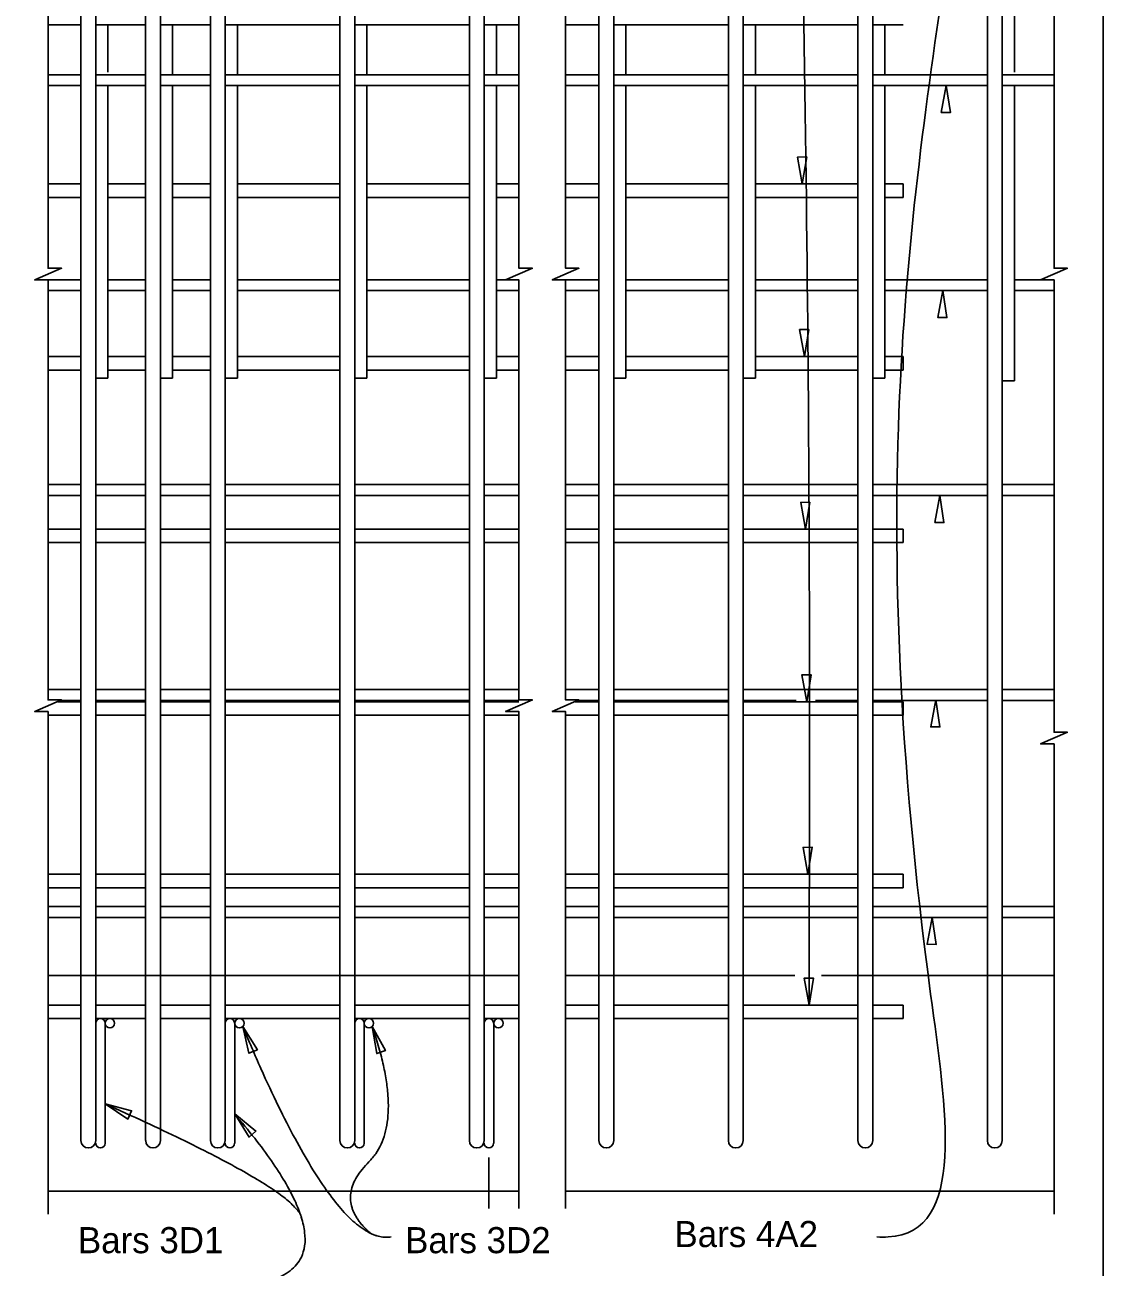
# Model space of a CAD drawing. Extents: x 0 to 20.5, y 0 to 12.9.
# Drawn here: x 16.322 to 20.485, y 4.445 to 9.244 of the extents above; entities that cross this region are included whole.
import ezdxf

# ---------------------------------------------------------------- set-up
doc = ezdxf.new("R2010")
doc.units = 0
for name, color, linetype in [('ActivePts-ConstElements', 7, 'Continuous'), ('BeamConc', 7, 'Continuous'), ('BeamConc_h', 7, 'Continuous'), ('Dimension', 7, 'Continuous'), ('Rebar', 7, 'Continuous'), ('TextStructures', 7, 'Continuous')]:
    doc.layers.add(name, color=color, linetype=linetype)

msp = doc.modelspace()

# ---------------------------------------------------------------- linework, layer by layer
at = {"layer": 'ActivePts-ConstElements'}
msp.add_lwpolyline([(0, 12.9475), (20.485, 12.9475), (20.485, 0), (0, 0)], close=True, dxfattribs=at)
at = {"layer": 'BeamConc'}
for p, q in [((16.4116, 4.739), (18.2295, 4.739)), ((18.4095, 4.739), (20.2953, 4.739))]:
    msp.add_line(p, q, dxfattribs=at)
at = {"layer": 'BeamConc_h'}
for p, q in [((16.4116, 5.5723), (18.2295, 5.5723)), ((18.4095, 5.5723), (19.2946, 5.5723)), ((19.3975, 5.5723), (20.2953, 5.5723))]:
    msp.add_line(p, q, dxfattribs=at)
at = {"layer": 'Dimension'}
msp.add_line((18.1135, 4.8686), (18.1135, 4.6717), dxfattribs=at)
for points in [[(16.4116, 10.0723), (16.4116, 8.3039), (16.4633, 8.3039), (16.36, 8.2589), (16.4116, 8.2589), (16.4116, 6.6365), (16.4633, 6.6365), (16.36, 6.5915), (16.4116, 6.5915), (16.4116, 4.6506)], [(18.2295, 10.0723), (18.2295, 8.3039), (18.2812, 8.3039), (18.1778, 8.2589), (18.2295, 8.2589), (18.2295, 6.6365), (18.2812, 6.6365), (18.1778, 6.5915), (18.2295, 6.5915), (18.2295, 4.6717)], [(18.4095, 10.0723), (18.4095, 8.3039), (18.4612, 8.3039), (18.3579, 8.2589), (18.4095, 8.2589), (18.4095, 6.6365), (18.4612, 6.6365), (18.3579, 6.5915), (18.4095, 6.5915), (18.4095, 4.6717)], [(20.2953, 10.0723), (20.2953, 8.3039), (20.347, 8.3039), (20.2437, 8.2589), (20.2953, 8.2589), (20.2953, 6.5115), (20.347, 6.5115), (20.2437, 6.4665), (20.2953, 6.4665), (20.2953, 4.6506)]]:
    msp.add_lwpolyline(points, dxfattribs=at)
for points in [[(19.8792, 9.0099), (19.8601, 8.906), (19.8953, 8.9055)], [(19.3235, 8.6296), (19.3404, 8.7339), (19.3051, 8.7336)], [(19.8656, 8.2178), (19.8465, 8.1139), (19.8818, 8.1134)], [(19.3313, 7.9628), (19.3482, 8.067), (19.3129, 8.0668)], [(19.3355, 7.2956), (19.3525, 7.3999), (19.3172, 7.3996)], [(19.8543, 7.4259), (19.8352, 7.3221), (19.8704, 7.3216)], [(19.3403, 6.6295), (19.3572, 6.7338), (19.322, 6.7335)], [(19.8387, 6.6364), (19.8196, 6.5325), (19.8549, 6.532)], [(19.3451, 5.9629), (19.362, 6.0671), (19.3267, 6.0669)], [(19.8246, 5.7963), (19.8055, 5.6925), (19.8408, 5.692)], [(19.3494, 5.4578), (19.3664, 5.562), (19.3311, 5.5618)], [(17.1629, 5.3745), (17.1867, 5.2716), (17.2193, 5.2852)], [(17.6629, 5.3745), (17.6802, 5.2703), (17.7135, 5.2818)], [(16.6318, 5.0758), (16.7197, 5.0172), (16.734, 5.0494)], [(17.1318, 5.0372), (17.1876, 4.9476), (17.214, 4.9709)]]:
    msp.add_lwpolyline(points, close=True, dxfattribs=at)
for points in [[(19.5169, 10.7039), (19.4625, 10.7051), (19.3121, 10.2105), (19.3494, 5.4578)], [(19.6115, 4.5619), (19.6547, 4.5619), (19.819, 5.4995), (19.8873, 9.5318)]]:
    msp.add_spline(points, degree=3, dxfattribs=at)
for points in [[(17.7362, 4.5622), (17.5173, 4.5252), (17.1629, 5.3745)], [(17.6567, 4.5757), (17.5049, 4.7071), (17.7938, 4.995), (17.6629, 5.3745)], [(17.3904, 4.6335), (17.3739, 4.7442), (16.6318, 5.0758)], [(17.0406, 4.3694), (17.7177, 4.3524), (17.1318, 5.0372)]]:
    msp.add_open_spline(points, degree=2, dxfattribs=at)
at = {"layer": 'Rebar'}
for p, q in [((16.5953, 4.9343), (16.5953, 10.4187)), ((16.8453, 4.9343), (16.8453, 10.4187)), ((17.0953, 4.9343), (17.0953, 10.4187)), ((17.5953, 4.9343), (17.5953, 10.4187)), ((18.0953, 4.9343), (18.0953, 10.4187)), ((18.5953, 4.9343), (18.5953, 10.4187)), ((19.0953, 4.9343), (19.0953, 10.4187)), ((19.5953, 4.9343), (19.5953, 10.4187)), ((20.0953, 4.9343), (20.0953, 10.4187)), ((20.1422, 9.0619), (20.1422, 9.8475)), ((16.538, 4.9343), (16.538, 9.5318)), ((16.788, 4.9343), (16.788, 9.5318)), ((17.038, 4.9343), (17.038, 9.5318)), ((17.538, 4.9343), (17.538, 9.5318)), ((18.038, 4.9343), (18.038, 9.5318)), ((18.538, 4.9343), (18.538, 9.5318)), ((19.038, 4.9343), (19.038, 9.5318)), ((19.538, 4.9343), (19.538, 9.5318)), ((20.038, 4.9343), (20.038, 9.5318)), ((16.4116, 9.2443), (16.538, 9.2443)), ((16.5953, 9.2443), (16.788, 9.2443)), ((16.6422, 9.0619), (16.6422, 9.2443)), ((16.8453, 9.2443), (17.038, 9.2443)), ((16.8922, 9.0515), (16.8922, 9.2443)), ((17.0953, 9.2443), (17.538, 9.2443)), ((17.1422, 9.0515), (17.1422, 9.2443)), ((17.5953, 9.2443), (18.038, 9.2443)), ((17.6422, 9.0515), (17.6422, 9.2443)), ((18.0953, 9.2443), (18.2295, 9.2443)), ((18.1422, 9.0515), (18.1422, 9.2443)), ((18.4095, 9.2443), (18.538, 9.2443)), ((18.5953, 9.2443), (19.038, 9.2443)), ((18.6422, 9.0515), (18.6422, 9.2443)), ((19.0953, 9.2443), (19.538, 9.2443)), ((19.1422, 9.0515), (19.1422, 9.2443)), ((19.5953, 9.2443), (19.7125, 9.2443)), ((19.6422, 9.0515), (19.6422, 9.2443)), ((16.4116, 9.0515), (16.538, 9.0515)), ((16.5953, 9.0515), (16.788, 9.0515)), ((16.8453, 9.0515), (17.038, 9.0515)), ((17.0953, 9.0515), (17.538, 9.0515)), ((17.5953, 9.0515), (18.038, 9.0515)), ((18.0953, 9.0515), (18.2295, 9.0515)), ((18.4095, 9.0515), (18.538, 9.0515)), ((18.5953, 9.0515), (19.038, 9.0515)), ((19.0953, 9.0515), (19.538, 9.0515)), ((19.5953, 9.0515), (20.038, 9.0515)), ((20.0953, 9.0515), (20.2953, 9.0515)), ((16.4116, 9.0099), (16.538, 9.0099)), ((16.5953, 9.0099), (16.788, 9.0099)), ((16.6422, 7.8796), (16.6422, 9.0099)), ((16.8453, 9.0099), (17.038, 9.0099)), ((16.8922, 7.8796), (16.8922, 9.0099)), ((17.0953, 9.0099), (17.538, 9.0099)), ((17.1422, 7.8796), (17.1422, 9.0099)), ((17.5953, 9.0099), (18.038, 9.0099)), ((17.6422, 7.8796), (17.6422, 9.0099)), ((18.0953, 9.0099), (18.2295, 9.0099)), ((18.1422, 7.8796), (18.1422, 9.0099)), ((18.4095, 9.0099), (18.538, 9.0099)), ((18.5953, 9.0099), (19.038, 9.0099)), ((18.6422, 7.8796), (18.6422, 9.0099)), ((19.0953, 9.0099), (19.538, 9.0099)), ((19.1422, 7.8796), (19.1422, 9.0099)), ((19.5953, 9.0099), (20.038, 9.0099)), ((19.6422, 7.8796), (19.6422, 9.0099)), ((20.0953, 9.0099), (20.2953, 9.0099)), ((20.1422, 7.8692), (20.1422, 9.0099)), ((16.4116, 8.6296), (16.538, 8.6296)), ((16.6422, 8.6296), (16.788, 8.6296)), ((16.8922, 8.6296), (17.038, 8.6296)), ((17.1422, 8.6296), (17.538, 8.6296)), ((17.6422, 8.6296), (18.038, 8.6296)), ((18.1422, 8.6296), (18.2295, 8.6296)), ((18.4095, 8.6296), (18.538, 8.6296)), ((18.6422, 8.6296), (19.038, 8.6296)), ((19.1422, 8.6296), (19.538, 8.6296)), ((19.6422, 8.6296), (19.7125, 8.6296)), ((19.7125, 8.6296), (19.7125, 8.5776)), ((16.4116, 8.5776), (16.538, 8.5776)), ((16.6422, 8.5776), (16.788, 8.5776)), ((16.8922, 8.5776), (17.038, 8.5776)), ((17.1422, 8.5776), (17.538, 8.5776)), ((17.6422, 8.5776), (18.038, 8.5776)), ((18.1422, 8.5776), (18.2295, 8.5776)), ((18.4095, 8.5776), (18.538, 8.5776)), ((18.6422, 8.5776), (19.038, 8.5776)), ((19.1422, 8.5776), (19.538, 8.5776)), ((19.6422, 8.5776), (19.7125, 8.5776)), ((16.4116, 8.2598), (16.538, 8.2598)), ((16.6422, 8.2598), (16.788, 8.2598)), ((16.8922, 8.2598), (17.038, 8.2598)), ((17.1422, 8.2598), (17.538, 8.2598)), ((17.6422, 8.2598), (18.038, 8.2598)), ((18.1422, 8.2598), (18.2295, 8.2598)), ((18.4095, 8.2598), (18.538, 8.2598)), ((18.6422, 8.2598), (19.038, 8.2598)), ((19.1422, 8.2598), (19.538, 8.2598)), ((19.6422, 8.2598), (20.038, 8.2598)), ((20.1422, 8.2598), (20.2953, 8.2598)), ((16.4116, 8.2182), (16.538, 8.2182)), ((16.6422, 8.2182), (16.788, 8.2182)), ((16.8922, 8.2182), (17.038, 8.2182)), ((17.1422, 8.2182), (17.538, 8.2182)), ((17.6422, 8.2182), (18.038, 8.2182)), ((18.1422, 8.2182), (18.2295, 8.2182)), ((18.4095, 8.2182), (18.538, 8.2182)), ((18.6422, 8.2182), (19.038, 8.2182)), ((19.1422, 8.2182), (19.538, 8.2182)), ((19.6422, 8.2182), (20.038, 8.2182)), ((20.1422, 8.2182), (20.2953, 8.2182)), ((16.4116, 7.9629), (16.538, 7.9629)), ((16.6422, 7.9629), (16.788, 7.9629)), ((16.8922, 7.9629), (17.038, 7.9629)), ((17.1422, 7.9629), (17.538, 7.9629)), ((17.6422, 7.9629), (18.038, 7.9629)), ((18.1422, 7.9629), (18.2295, 7.9629)), ((18.4095, 7.9629), (18.538, 7.9629)), ((18.6422, 7.9629), (19.038, 7.9629)), ((19.1422, 7.9629), (19.538, 7.9629)), ((19.6422, 7.9629), (19.7125, 7.9629)), ((19.7125, 7.9629), (19.7125, 7.9109)), ((16.4116, 7.9109), (16.538, 7.9109)), ((16.6422, 7.8796), (16.5953, 7.8796)), ((16.6422, 7.9109), (16.788, 7.9109)), ((16.8922, 7.8796), (16.8453, 7.8796)), ((16.8922, 7.9109), (17.038, 7.9109)), ((17.1422, 7.8796), (17.0953, 7.8796)), ((17.1422, 7.9109), (17.538, 7.9109)), ((17.6422, 7.8796), (17.5953, 7.8796)), ((17.6422, 7.9109), (18.038, 7.9109)), ((18.1422, 7.8796), (18.0953, 7.8796)), ((18.1422, 7.9109), (18.2295, 7.9109)), ((18.4095, 7.9109), (18.538, 7.9109)), ((18.6422, 7.8796), (18.5953, 7.8796)), ((18.6422, 7.9109), (19.038, 7.9109)), ((19.1422, 7.8796), (19.0953, 7.8796)), ((19.1422, 7.9109), (19.538, 7.9109)), ((19.6422, 7.8796), (19.5953, 7.8796)), ((19.6422, 7.9109), (19.7125, 7.9109)), ((20.1422, 7.8692), (20.0953, 7.8692)), ((16.4116, 7.4681), (16.538, 7.4681)), ((16.5953, 7.4681), (16.788, 7.4681)), ((16.8453, 7.4681), (17.038, 7.4681)), ((17.0953, 7.4681), (17.538, 7.4681)), ((17.5953, 7.4681), (18.038, 7.4681)), ((18.0953, 7.4681), (18.2295, 7.4681)), ((18.4095, 7.4681), (18.538, 7.4681)), ((18.5953, 7.4681), (19.038, 7.4681)), ((19.0953, 7.4681), (19.538, 7.4681)), ((19.5953, 7.4681), (20.038, 7.4681)), ((20.0953, 7.4681), (20.2953, 7.4681)), ((16.4116, 7.4265), (16.538, 7.4265)), ((16.5953, 7.4265), (16.788, 7.4265)), ((16.8453, 7.4265), (17.038, 7.4265)), ((17.0953, 7.4265), (17.538, 7.4265)), ((17.5953, 7.4265), (18.038, 7.4265)), ((18.0953, 7.4265), (18.2295, 7.4265)), ((18.4095, 7.4265), (18.538, 7.4265)), ((18.5953, 7.4265), (19.038, 7.4265)), ((19.0953, 7.4265), (19.538, 7.4265)), ((19.5953, 7.4265), (20.038, 7.4265)), ((20.0953, 7.4265), (20.2953, 7.4265)), ((16.4116, 7.2962), (16.538, 7.2962)), ((16.5953, 7.2962), (16.788, 7.2962)), ((16.8453, 7.2962), (17.038, 7.2962)), ((17.0953, 7.2962), (17.538, 7.2962)), ((17.5953, 7.2962), (18.038, 7.2962)), ((18.0953, 7.2962), (18.2295, 7.2962)), ((18.4095, 7.2962), (18.538, 7.2962)), ((18.5953, 7.2962), (19.038, 7.2962)), ((19.0953, 7.2962), (19.538, 7.2962)), ((19.5953, 7.2962), (19.7125, 7.2962)), ((19.7125, 7.2962), (19.7125, 7.2442)), ((16.4116, 7.2442), (16.538, 7.2442)), ((16.5953, 7.2442), (16.788, 7.2442)), ((16.8453, 7.2442), (17.038, 7.2442)), ((17.0953, 7.2442), (17.538, 7.2442)), ((17.5953, 7.2442), (18.038, 7.2442)), ((18.0953, 7.2442), (18.2295, 7.2442)), ((18.4095, 7.2442), (18.538, 7.2442)), ((18.5953, 7.2442), (19.038, 7.2442)), ((19.0953, 7.2442), (19.538, 7.2442)), ((19.5953, 7.2442), (19.7125, 7.2442)), ((16.4116, 6.6764), (16.538, 6.6764)), ((16.5953, 6.6764), (16.788, 6.6764)), ((16.8453, 6.6764), (17.038, 6.6764)), ((17.0953, 6.6764), (17.538, 6.6764)), ((17.5953, 6.6764), (18.038, 6.6764)), ((18.0953, 6.6764), (18.2295, 6.6764)), ((18.4095, 6.6764), (18.538, 6.6764)), ((18.5953, 6.6764), (19.038, 6.6764)), ((19.0953, 6.6764), (19.538, 6.6764)), ((19.5953, 6.6764), (20.038, 6.6764)), ((20.0953, 6.6764), (20.2953, 6.6764)), ((16.449, 6.6296), (16.538, 6.6296)), ((16.4603, 6.6348), (16.538, 6.6348)), ((16.5953, 6.6348), (16.788, 6.6348)), ((16.5953, 6.6295), (16.788, 6.6295)), ((16.8453, 6.6348), (17.038, 6.6348)), ((16.8453, 6.6296), (17.038, 6.6296)), ((17.0953, 6.6348), (17.538, 6.6348)), ((17.0953, 6.6296), (17.538, 6.6296)), ((17.5953, 6.6348), (18.038, 6.6348)), ((17.5953, 6.6296), (18.038, 6.6296)), ((18.0953, 6.6348), (18.2295, 6.6348)), ((18.0953, 6.6296), (18.2295, 6.6296)), ((18.447, 6.6296), (18.538, 6.6296)), ((18.4582, 6.6348), (18.538, 6.6348)), ((18.5953, 6.6348), (19.038, 6.6348)), ((18.5953, 6.6296), (19.038, 6.6296)), ((19.0953, 6.6348), (19.2997, 6.6348)), ((19.0953, 6.6296), (19.538, 6.6296)), ((19.3742, 6.6348), (19.538, 6.6348)), ((19.5953, 6.6348), (20.038, 6.6348)), ((19.5953, 6.6296), (19.7125, 6.6296)), ((19.7125, 6.6296), (19.7125, 6.5775)), ((20.0953, 6.6348), (20.2953, 6.6348)), ((16.4116, 6.5774), (16.538, 6.5774)), ((16.5953, 6.5775), (16.788, 6.5775)), ((16.8453, 6.5775), (17.038, 6.5775)), ((17.0953, 6.5775), (17.538, 6.5775)), ((17.5953, 6.5775), (18.038, 6.5775)), ((18.0953, 6.5775), (18.2295, 6.5775)), ((18.4095, 6.5775), (18.538, 6.5775)), ((18.5953, 6.5775), (19.038, 6.5775)), ((19.0953, 6.5775), (19.538, 6.5775)), ((19.5953, 6.5775), (19.7125, 6.5775)), ((16.4116, 5.9628), (16.538, 5.9628)), ((16.5953, 5.9628), (16.788, 5.9628)), ((16.8453, 5.9628), (17.038, 5.9628)), ((17.0953, 5.9628), (17.538, 5.9628)), ((17.5953, 5.9628), (18.038, 5.9628)), ((18.0953, 5.9628), (18.2295, 5.9628)), ((18.4095, 5.9628), (18.538, 5.9628)), ((18.5953, 5.9628), (19.038, 5.9628)), ((19.0953, 5.9628), (19.538, 5.9628)), ((19.5953, 5.9628), (19.7125, 5.9628)), ((19.7125, 5.9628), (19.7125, 5.9108)), ((16.4116, 5.9108), (16.538, 5.9108)), ((16.5953, 5.9108), (16.788, 5.9108)), ((16.8453, 5.9108), (17.038, 5.9108)), ((17.0953, 5.9108), (17.538, 5.9108)), ((17.5953, 5.9108), (18.038, 5.9108)), ((18.0953, 5.9108), (18.2295, 5.9108)), ((18.4095, 5.9108), (18.538, 5.9108)), ((18.5953, 5.9108), (19.038, 5.9108)), ((19.0953, 5.9108), (19.538, 5.9108)), ((19.5953, 5.9108), (19.7125, 5.9108)), ((16.4116, 5.838), (16.538, 5.838)), ((16.5953, 5.838), (16.788, 5.838)), ((16.8453, 5.838), (17.038, 5.838)), ((17.0953, 5.838), (17.538, 5.838)), ((17.5953, 5.838), (18.038, 5.838)), ((18.0953, 5.838), (18.2295, 5.838)), ((18.4095, 5.838), (18.538, 5.838)), ((18.5953, 5.838), (19.038, 5.838)), ((19.0953, 5.838), (19.538, 5.838)), ((19.5953, 5.838), (20.038, 5.838)), ((20.0953, 5.838), (20.2953, 5.838)), ((16.4116, 5.7963), (16.538, 5.7963)), ((16.5953, 5.7963), (16.788, 5.7963)), ((16.8453, 5.7963), (17.038, 5.7963)), ((17.0953, 5.7963), (17.538, 5.7963)), ((17.5953, 5.7963), (18.038, 5.7963)), ((18.0953, 5.7963), (18.2295, 5.7963)), ((18.4095, 5.7963), (18.538, 5.7963)), ((18.5953, 5.7963), (19.038, 5.7963)), ((19.0953, 5.7963), (19.538, 5.7963)), ((19.5953, 5.7963), (20.038, 5.7963)), ((20.0953, 5.7963), (20.2953, 5.7963)), ((16.4116, 5.4577), (16.538, 5.4577)), ((16.5953, 5.4577), (16.788, 5.4577)), ((16.8453, 5.4577), (17.038, 5.4577)), ((17.0953, 5.4577), (17.538, 5.4577)), ((17.5953, 5.4577), (18.038, 5.4577)), ((18.0953, 5.4577), (18.2295, 5.4577)), ((18.4095, 5.4577), (18.538, 5.4577)), ((18.5953, 5.4577), (19.038, 5.4577)), ((19.0953, 5.4577), (19.538, 5.4577)), ((19.5953, 5.4577), (19.7125, 5.4577)), ((19.7125, 5.4577), (19.7125, 5.4057)), ((16.4116, 5.4057), (16.538, 5.4057)), ((16.5953, 5.4057), (16.788, 5.4057)), ((16.6318, 5.3874), (16.6318, 4.9239)), ((16.8453, 5.4057), (17.038, 5.4057)), ((17.0953, 5.4057), (17.538, 5.4057)), ((17.1318, 5.3874), (17.1318, 4.9239)), ((17.5953, 5.4057), (18.038, 5.4057)), ((17.6318, 5.3874), (17.6318, 4.9239)), ((18.0953, 5.4057), (18.2295, 5.4057)), ((18.1318, 5.3874), (18.1318, 4.9239)), ((18.4095, 5.4057), (18.538, 5.4057)), ((18.5953, 5.4057), (19.038, 5.4057)), ((19.0953, 5.4057), (19.538, 5.4057)), ((19.5953, 5.4057), (19.7125, 5.4057))]:
    msp.add_line(p, q, dxfattribs=at)
for centre in [(16.65, 5.3874), (17.15, 5.3874), (17.65, 5.3874), (18.15, 5.3874)]:
    msp.add_circle(centre, 0.0182, dxfattribs=at)
for centre, radius, start, end in [((16.6135, 5.3874), 0.0182, 0, 180), ((17.1135, 5.3874), 0.0182, 0, 180), ((17.6135, 5.3874), 0.0182, 0, 180), ((18.1135, 5.3874), 0.0182, 0, 180), ((16.5667, 4.9343), 0.0286, 180, 0), ((16.6135, 4.9239), 0.0182, 180, 0), ((16.8167, 4.9343), 0.0286, 180, 0), ((17.0667, 4.9343), 0.0286, 180, 0), ((17.1135, 4.9239), 0.0182, 180, 0), ((17.5667, 4.9343), 0.0286, 180, 0), ((17.6135, 4.9239), 0.0182, 180, 0), ((18.0667, 4.9343), 0.0286, 180, 0), ((18.1135, 4.9239), 0.0182, 180, 0), ((18.5667, 4.9343), 0.0286, 180, 0), ((19.0667, 4.9343), 0.0286, 180, 0), ((19.5667, 4.9343), 0.0286, 180, 0), ((20.0667, 4.9343), 0.0286, 180, 0)]:
    msp.add_arc(centre, radius, start, end, dxfattribs=at)

# ---------------------------------------------------------------- texts
at = {"layer": 'Dimension'}
for s, p in [('Bars 3D1 ', (16.5264, 4.4992)), ('Bars 3D2 ', (17.7898, 4.4992))]:
    msp.add_text(s, height=0.1008, dxfattribs=at).set_placement(p)
at = {"layer": 'TextStructures'}
msp.add_text('Bars 4A2', height=0.1008, dxfattribs=at).set_placement((18.8297, 4.5229))

doc.saveas('drawing.dxf')
